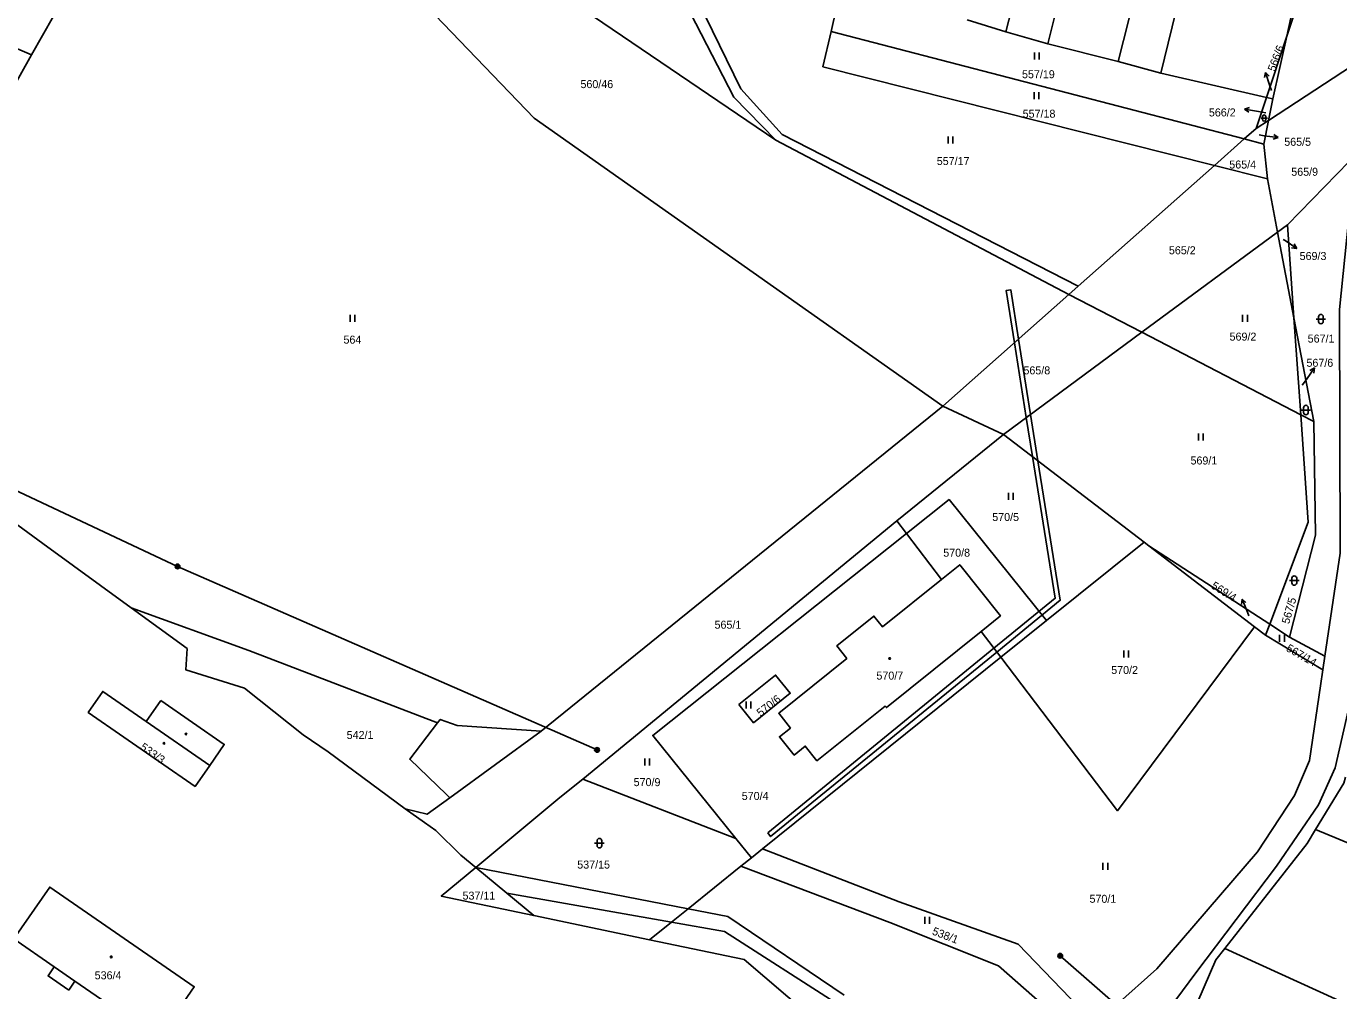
# Model space of a CAD drawing. Extents: x -757266 to -753360, y -1162585 to -1157740.
# Drawn here: x -756391.6 to -756112.8, y -1161498.7 to -1161293.7 of the extents above; entities that cross this region are included whole.
import ezdxf

# ---------------------------------------------------------------- set-up
doc = ezdxf.new("R2010")
doc.units = 0
for name, color, linetype in [('Hranice parcel', 7, 'Continuous'), ('Parcelní čísla', 7, 'Continuous'), ('Pop  PČ popisy', 7, 'Continuous'), ('Poz předměty', 7, 'Continuous'), ('Vnitřní kresba', 7, 'Continuous'), ('Věcná břemena k části', 7, 'Continuous'), ('Značky budov', 7, 'Continuous'), ('Značky kultur', 7, 'Continuous')]:
    doc.layers.add(name, color=color, linetype=linetype)

msp = doc.modelspace()

# ---------------------------------------------------------------- linework, layer by layer
at = {"layer": 'Hranice parcel'}
for p, q in [((-756183.54, -1161294.9), (-756158.99, -1161200.59)), ((-756159.65, -1161301.26), (-756140.24, -1161223.45)), ((-756150.62, -1161303.75), (-756133.64, -1161234.26)), ((-756232.35, -1161317.96), (-756311.49, -1161264.23)), ((-756376.54, -1161275.16), (-756390.46, -1161299.8)), ((-756183.54, -1161294.9), (-756191.74, -1161292.41)), ((-756132.86, -1161317.7), (-756220.64, -1161294.84)), ((-756174.59, -1161297.48), (-756183.54, -1161294.9)), ((-756128.17, -1161308.89), (-756123.86, -1161295.88)), ((-756123.86, -1161295.88), (-756126.82, -1161309.2)), ((-756159.65, -1161301.26), (-756174.59, -1161297.48)), ((-756390.46, -1161299.8), (-756397.42, -1161312.12)), ((-756150.62, -1161303.75), (-756159.65, -1161301.26)), ((-756128.17, -1161308.89), (-756150.62, -1161303.75)), ((-756130.35, -1161315.48), (-756128.17, -1161308.89)), ((-756126.82, -1161309.2), (-756128.17, -1161308.89)), ((-756126.82, -1161309.2), (-756127.73, -1161313.77)), ((-756132.86, -1161317.7), (-756130.35, -1161315.48)), ((-756127.73, -1161313.77), (-756130.35, -1161315.48)), ((-756128.73, -1161318.78), (-756127.73, -1161313.77)), ((-756232.35, -1161317.96), (-756170.13, -1161350.73)), ((-756139.21, -1161323.33), (-756132.86, -1161317.7)), ((-756128.73, -1161318.78), (-756132.86, -1161317.7)), ((-756127.96, -1161326.17), (-756128.73, -1161318.78)), ((-756139.21, -1161323.33), (-756168.18, -1161349.01)), ((-756127.96, -1161326.17), (-756139.21, -1161323.33)), ((-756110.57, -1161322.52), (-756123.68, -1161335.95)), ((-756125.79, -1161337.51), (-756127.96, -1161326.17)), ((-756125.79, -1161337.51), (-756154.62, -1161358.78)), ((-756123.68, -1161335.95), (-756125.79, -1161337.51)), ((-756122.31, -1161355.7), (-756125.79, -1161337.51)), ((-756122.31, -1161355.7), (-756123.68, -1161335.95)), ((-756170.13, -1161350.73), (-756168.18, -1161349.01)), ((-756170.13, -1161350.73), (-756196.92, -1161374.48)), ((-756154.62, -1161358.78), (-756170.13, -1161350.73)), ((-756120.89, -1161376.29), (-756122.31, -1161355.7)), ((-756122.31, -1161355.7), (-756118.1, -1161377.74)), ((-756184.02, -1161380.47), (-756154.62, -1161358.78)), ((-756120.89, -1161376.29), (-756154.62, -1161358.78)), ((-756184.02, -1161380.47), (-756196.92, -1161374.48)), ((-756118.1, -1161377.74), (-756120.89, -1161376.29)), ((-756206.66, -1161398.84), (-756184.02, -1161380.47)), ((-756154.15, -1161403.37), (-756184.02, -1161380.47)), ((-756273.4, -1161453.73), (-756206.66, -1161398.84)), ((-756206.66, -1161398.84), (-756204.62, -1161401.53)), ((-756197.18, -1161411.3), (-756204.62, -1161401.53)), ((-756154.15, -1161403.37), (-756174.87, -1161420.03)), ((-756153.17, -1161404.13), (-756154.15, -1161403.37)), ((-756130.72, -1161421.34), (-756153.17, -1161404.13)), ((-756153.17, -1161404.13), (-756127.46, -1161420.82)), ((-756174.87, -1161420.03), (-756184.59, -1161427.85)), ((-756128.34, -1161423.17), (-756130.72, -1161421.34)), ((-756128.34, -1161423.17), (-756127.46, -1161420.82)), ((-756127.46, -1161420.82), (-756123.26, -1161423.55)), ((-756184.59, -1161427.85), (-756188.79, -1161422.33)), ((-756116.17, -1161430.5), (-756128.34, -1161423.17)), ((-756123.26, -1161423.55), (-756115.74, -1161427.59)), ((-756184.59, -1161427.85), (-756235.19, -1161468.54)), ((-756115.74, -1161427.59), (-756116.17, -1161430.5)), ((-756240.87, -1161466.34), (-756273.4, -1161453.73)), ((-756237.56, -1161470.45), (-756240.87, -1161466.34)), ((-756235.19, -1161468.54), (-756237.56, -1161470.45)), ((-756237.56, -1161470.45), (-756239.79, -1161472.24)), ((-756259.22, -1161487.86), (-756283.77, -1161482.71))]:
    msp.add_line(p, q, dxfattribs=at)
for points in [[(-756390.46, -1161299.8), (-756481.22, -1161260.78), (-756640.9, -1161209.51), (-756684.73, -1161196.86)], [(-756174.59, -1161297.48), (-756167.09, -1161267.4), (-756151.83, -1161208.72)], [(-756196.92, -1161374.48), (-756283.73, -1161313.29), (-756324.07, -1161271.22), (-756357.02, -1161240.62)], [(-756272.42, -1161248.36), (-756241.28, -1161308.82), (-756232.35, -1161317.96)], [(-756168.18, -1161349.01), (-756231.02, -1161316.75), (-756239.84, -1161307.07), (-756265.47, -1161254.47)], [(-756123.86, -1161295.88), (-756121.39, -1161284.75), (-756121.69, -1161269.85)], [(-756123.86, -1161295.88), (-756120.03, -1161284.31), (-756121.69, -1161269.85)], [(-756220.64, -1161294.84), (-756219.55, -1161290.1), (-756217.24, -1161284.88)], [(-756139.21, -1161323.33), (-756222.36, -1161302.35), (-756220.64, -1161294.84)], [(-756097.95, -1161294.3), (-756102.88, -1161297.52), (-756105.97, -1161299.54), (-756127.73, -1161313.77)], [(-756110.57, -1161322.52), (-756109.94, -1161327.5), (-756112.65, -1161353.91), (-756112.52, -1161405.74), (-756115.74, -1161427.59)], [(-756369.33, -1161417.3), (-756388.09, -1161403.64), (-756428.45, -1161374.14), (-756432.89, -1161370.9)], [(-756304.22, -1161441.76), (-756303.68, -1161441.05), (-756300.04, -1161442.35), (-756282.26, -1161443.56), (-756196.92, -1161374.48)], [(-756127.46, -1161420.82), (-756119.31, -1161399.1), (-756120.89, -1161376.29)], [(-756118.1, -1161377.74), (-756117.77, -1161401.91), (-756123.26, -1161423.55)], [(-756204.62, -1161401.53), (-756195.59, -1161394.34), (-756174.87, -1161420.03)], [(-756204.62, -1161401.53), (-756258.51, -1161444.43), (-756240.87, -1161466.34)], [(-756197.18, -1161411.3), (-756193.32, -1161408.19), (-756184.68, -1161419.02), (-756188.79, -1161422.33)], [(-756188.79, -1161422.33), (-756208.9, -1161438.53), (-756209.17, -1161438.2), (-756223.64, -1161449.84), (-756226.14, -1161446.72), (-756228.46, -1161448.61), (-756231.62, -1161444.72), (-756229.28, -1161442.87), (-756231.77, -1161439.72), (-756217.31, -1161428.08), (-756219.42, -1161425.43), (-756211.54, -1161419.1), (-756209.69, -1161421.4), (-756197.18, -1161411.3)], [(-756304.22, -1161441.76), (-756344.31, -1161426.42), (-756369.33, -1161417.3)], [(-756311.11, -1161460.07), (-756327.45, -1161447.94), (-756332.78, -1161444.32), (-756345.23, -1161434.4), (-756357.68, -1161430.51), (-756357.42, -1161425.98), (-756369.33, -1161417.3)], [(-756130.72, -1161421.34), (-756159.77, -1161460.46), (-756184.59, -1161427.85)], [(-756240.23, -1161437.87), (-756232.44, -1161431.61), (-756229.31, -1161435.5), (-756237.1, -1161441.77), (-756240.23, -1161437.87)], [(-756116.17, -1161430.5), (-756116.67, -1161433.93), (-756118.99, -1161449.78), (-756122.19, -1161457.23), (-756130.08, -1161469.19), (-756151.46, -1161494.02), (-756159.98, -1161501.7), (-756162.48, -1161507.9)], [(-756363.02, -1161437.03), (-756366.1, -1161441.5), (-756375.37, -1161435.09), (-756378.42, -1161439.57), (-756355.74, -1161455.29), (-756352.64, -1161450.81), (-756349.56, -1161446.37), (-756363.02, -1161437.03)], [(-756159.42, -1161516.46), (-756154.69, -1161510.47), (-756143.16, -1161494.88), (-756126.02, -1161472.23), (-756117.13, -1161459.17), (-756113.58, -1161451.3), (-756109.9, -1161435.2), (-756109.66, -1161433.84)], [(-756311.11, -1161460.07), (-756306.45, -1161461.21), (-756301.62, -1161457.69), (-756302.35, -1161456.99), (-756310.15, -1161449.5), (-756304.22, -1161441.76)], [(-756296.1, -1161472.53), (-756278.27, -1161457.64), (-756273.4, -1161453.73)], [(-756117.72, -1161464.44), (-756111.7, -1161454.56), (-756111.36, -1161453.31)], [(-756296.1, -1161472.53), (-756299.31, -1161469.92), (-756304.62, -1161464.68), (-756307.04, -1161462.96), (-756311.11, -1161460.07)], [(-756137.01, -1161489.71), (-756119.54, -1161467.41), (-756117.72, -1161464.44)], [(-756117.72, -1161464.44), (-756097.06, -1161473.04), (-756071.31, -1161481.14), (-756032.92, -1161490.7), (-756008.46, -1161495.88), (-755947.24, -1161511.38)], [(-756162.48, -1161507.9), (-756180.93, -1161488.82), (-756206.15, -1161479.79), (-756235.19, -1161468.54)], [(-756283.77, -1161482.71), (-756303.45, -1161478.57), (-756296.1, -1161472.53)], [(-756283.77, -1161482.71), (-756289.5, -1161477.98), (-756296.1, -1161472.53)], [(-756239.79, -1161472.24), (-756251.03, -1161481.27), (-756254.57, -1161484.12), (-756259.22, -1161487.86)], [(-756164.37, -1161513.8), (-756165.06, -1161511.03), (-756185.05, -1161493.42), (-756208.18, -1161484.23), (-756239.79, -1161472.24)], [(-756382.56, -1161498.55), (-756386.98, -1161495.54), (-756385.64, -1161493.6), (-756394.23, -1161487.68), (-756386.63, -1161476.66), (-756355.93, -1161497.86), (-756358.14, -1161501.05), (-756356.8, -1161502.03), (-756357.72, -1161503.5), (-756359.15, -1161502.51), (-756363.54, -1161508.85), (-756364.7, -1161510.75), (-756368.03, -1161508.5), (-756366.74, -1161506.64), (-756381.25, -1161496.69), (-756382.56, -1161498.55)], [(-756312.03, -1161681.9), (-756299.84, -1161658.1), (-756263.6, -1161631.64), (-756226.26, -1161593.42), (-756207.13, -1161563.22), (-756211.76, -1161515.41), (-756239.08, -1161492.08), (-756259.22, -1161487.86)], [(-756145.4, -1161507.2), (-756138.89, -1161492.11), (-756137.01, -1161489.71)], [(-756137.01, -1161489.71), (-756105.47, -1161504.07), (-756095.47, -1161507.48), (-756049.15, -1161519.68), (-755945.92, -1161541.61), (-755925.02, -1161547.7)]]:
    msp.add_lwpolyline(points, dxfattribs=at)
at = {"layer": 'Pop  PČ popisy'}
for p, q in [((-756128.377, -1161303.556), (-756128.544, -1161304.663)), ((-756127.45, -1161306.41), (-756128.377, -1161303.556)), ((-756128.377, -1161303.556), (-756127.592, -1161304.354)), ((-756127.12, -1161307.42), (-756127.45, -1161306.41)), ((-756132.835, -1161311.349), (-756131.762, -1161311.03)), ((-756129.88, -1161311.87), (-756132.835, -1161311.349)), ((-756132.835, -1161311.349), (-756131.936, -1161312.016)), ((-756128.29, -1161312.16), (-756129.88, -1161311.87)), ((-756129.73, -1161316.85), (-756128.64, -1161317)), ((-756128.64, -1161317), (-756125.668, -1161317.418)), ((-756125.668, -1161317.418), (-756126.73, -1161317.774)), ((-756125.668, -1161317.418), (-756126.59, -1161316.782)), ((-756124.58, -1161339.03), (-756124.2, -1161339.29)), ((-756124.2, -1161339.29), (-756121.712, -1161340.968)), ((-756121.712, -1161340.968), (-756122.822, -1161340.823)), ((-756121.712, -1161340.968), (-756122.262, -1161339.993)), ((-756120.54, -1161370.03), (-756119.68, -1161368.79)), ((-756119.68, -1161368.79), (-756117.959, -1161366.332)), ((-756117.959, -1161366.332), (-756118.943, -1161366.865)), ((-756117.959, -1161366.332), (-756118.123, -1161367.439)), ((-756133.344, -1161415.488), (-756133.433, -1161416.604)), ((-756132.22, -1161418.27), (-756133.344, -1161415.488)), ((-756133.344, -1161415.488), (-756132.505, -1161416.228)), ((-756131.9, -1161419.06), (-756132.22, -1161418.27))]:
    msp.add_line(p, q, dxfattribs=at)
at = {"layer": 'Poz předměty'}
for p, q in [((-756441.37, -1161370.14), (-756359.45, -1161408.54)), ((-756359.45, -1161408.54), (-756270.36, -1161447.53)), ((-756171.96, -1161491.28), (-756099.89, -1161554.11))]:
    msp.add_line(p, q, dxfattribs=at)
for centre, radius in [((-756359.4534, -1161408.5399), 0.5), ((-756359.4534, -1161408.5399), 0.4), ((-756359.4534, -1161408.5399), 0.3), ((-756359.4534, -1161408.5399), 0.2), ((-756359.4534, -1161408.5399), 0.1), ((-756270.3634, -1161447.5299), 0.5), ((-756270.3634, -1161447.5299), 0.4), ((-756270.3634, -1161447.5299), 0.3), ((-756270.3634, -1161447.5299), 0.2), ((-756270.3634, -1161447.5299), 0.1), ((-756171.9634, -1161491.2799), 0.5), ((-756171.9634, -1161491.2799), 0.4), ((-756171.9634, -1161491.2799), 0.3), ((-756171.9634, -1161491.2799), 0.2), ((-756171.9634, -1161491.2799), 0.1)]:
    msp.add_circle(centre, radius, dxfattribs=at)
at = {"layer": 'Vnitřní kresba'}
for p, q in [((-756366.1, -1161441.5), (-756352.64, -1161450.81)), ((-756301.62, -1161457.69), (-756282.26, -1161443.56)), ((-756296.1, -1161472.53), (-756251.03, -1161481.27)), ((-756289.5, -1161477.98), (-756254.57, -1161484.12)), ((-756251.03, -1161481.27), (-756242.54, -1161482.92)), ((-756242.54, -1161482.92), (-756217.83, -1161499.63)), ((-756254.57, -1161484.12), (-756243.27, -1161486.11)), ((-756219.01, -1161501.67), (-756243.27, -1161486.11)), ((-756385.64, -1161493.6), (-756381.25, -1161496.69))]:
    msp.add_line(p, q, dxfattribs=at)
at = {"layer": 'Věcná břemena k části'}
for points in [[(-756181.71, -1161361), (-756180.82, -1161360.21), (-756182.49, -1161349.75), (-756183.48, -1161349.91)], [(-756178.26, -1161376.22), (-756180.82, -1161360.21), (-756181.71, -1161361), (-756179.17, -1161376.89)], [(-756177.84, -1161385.21), (-756176.69, -1161386.09), (-756178.26, -1161376.22), (-756179.17, -1161376.89)], [(-756234.11, -1161465.17), (-756233.48, -1161465.94), (-756185.44, -1161426.73), (-756171.95, -1161415.72), (-756176.69, -1161386.09), (-756177.84, -1161385.21), (-756173.03, -1161415.3), (-756186.05, -1161425.93)]]:
    msp.add_lwpolyline(points, close=True, dxfattribs=at)
at = {"layer": 'Značky budov'}
for centre in [(-756208.1968, -1161428.0992), (-756357.6768, -1161444.1492), (-756362.3568, -1161446.1092), (-756373.5568, -1161491.5092)]:
    msp.add_circle(centre, 0.175, dxfattribs=at)
at = {"layer": 'Značky kultur'}
for p, q in [((-756177.451, -1161300.8), (-756177.451, -1161299.3)), ((-756176.45, -1161300.8), (-756176.45, -1161299.3)), ((-756177.521, -1161309.27), (-756177.521, -1161307.77)), ((-756176.52, -1161309.27), (-756176.52, -1161307.77)), ((-756128.975, -1161312.925), (-756128.975, -1161313.596)), ((-756128.305, -1161313.596), (-756128.305, -1161312.925)), ((-756129.311, -1161313.261), (-756127.969, -1161313.261)), ((-756195.781, -1161318.69), (-756195.781, -1161317.19)), ((-756194.78, -1161318.69), (-756194.78, -1161317.19)), ((-756322.831, -1161356.57), (-756322.831, -1161355.07)), ((-756321.83, -1161356.57), (-756321.83, -1161355.07)), ((-756133.221, -1161356.54), (-756133.221, -1161355.04)), ((-756132.22, -1161356.54), (-756132.22, -1161355.04)), ((-756117.591, -1161355.981), (-756115.589, -1161355.981)), ((-756117.091, -1161355.481), (-756117.091, -1161356.482)), ((-756116.089, -1161356.482), (-756116.089, -1161355.481)), ((-756120.771, -1161375.301), (-756118.769, -1161375.301)), ((-756120.271, -1161374.801), (-756120.271, -1161375.802)), ((-756119.269, -1161375.802), (-756119.269, -1161374.801)), ((-756142.571, -1161381.77), (-756142.571, -1161380.27)), ((-756141.57, -1161381.77), (-756141.57, -1161380.27)), ((-756182.941, -1161394.4), (-756182.941, -1161392.9)), ((-756181.94, -1161394.4), (-756181.94, -1161392.9)), ((-756123.241, -1161411.531), (-756121.239, -1161411.531)), ((-756122.741, -1161411.031), (-756122.741, -1161412.032)), ((-756121.739, -1161412.032), (-756121.739, -1161411.031)), ((-756125.361, -1161424.58), (-756125.361, -1161423.08)), ((-756124.36, -1161424.58), (-756124.36, -1161423.08)), ((-756158.481, -1161427.89), (-756158.481, -1161426.39)), ((-756157.48, -1161427.89), (-756157.48, -1161426.39)), ((-756238.681, -1161438.75), (-756238.681, -1161437.25)), ((-756237.68, -1161438.75), (-756237.68, -1161437.25)), ((-756260.181, -1161450.82), (-756260.181, -1161449.32)), ((-756259.18, -1161450.82), (-756259.18, -1161449.32)), ((-756270.861, -1161467.341), (-756268.859, -1161467.341)), ((-756270.361, -1161466.841), (-756270.361, -1161467.842)), ((-756269.359, -1161467.842), (-756269.359, -1161466.841)), ((-756162.881, -1161473.03), (-756162.881, -1161471.53)), ((-756161.88, -1161473.03), (-756161.88, -1161471.53)), ((-756200.731, -1161484.49), (-756200.731, -1161482.99)), ((-756199.73, -1161484.49), (-756199.73, -1161482.99))]:
    msp.add_line(p, q, dxfattribs=at)
for centre, radius, start, end in [((-756128.64, -1161312.9256), 0.335, 0, 180), ((-756128.64, -1161313.5956), 0.335, 180, 359.987886), ((-756116.59, -1161355.4809), 0.5, 0, 180), ((-756116.59, -1161356.4809), 0.5, 180, 359.987886), ((-756119.77, -1161374.8009), 0.5, 0, 180), ((-756119.77, -1161375.8009), 0.5, 180, 359.987886), ((-756122.24, -1161411.0309), 0.5, 0, 180), ((-756122.24, -1161412.0309), 0.5, 180, 359.987886), ((-756269.86, -1161466.8409), 0.5, 0, 180), ((-756269.86, -1161467.8409), 0.5, 180, 359.987886)]:
    msp.add_arc(centre, radius, start, end, dxfattribs=at)

# ---------------------------------------------------------------- texts
at = {"layer": 'Parcelní čísla'}
for s, rotation, p in [('566/6', 68.999997, (-756126.376, -1161303.504)), ('569/4', 328, (-756140.04, -1161413.07)), ('567/5', 74, (-756123.342, -1161420.874)), ('567/14', 329.999997, (-756124.135, -1161426.396)), ('570/6', 38, (-756235.625, -1161440.53)), ('533/3', 325, (-756367.567, -1161447.286)), ('538/1', 339, (-756199.314, -1161486.693))]:
    msp.add_text(s, height=1.7, rotation=rotation, dxfattribs=at).set_placement(p)
for s, p in [('557/19', (-756180.08, -1161304.79)), ('560/46', (-756273.88, -1161306.89)), ('557/18', (-756179.94, -1161313.18)), ('566/2', (-756140.387, -1161312.91)), ('565/5', (-756124.38, -1161319.148)), ('557/17', (-756198.19, -1161323.24)), ('565/4', (-756136.05, -1161323.98)), ('565/9', (-756122.89, -1161325.52)), ('565/2', (-756148.88, -1161342.2)), ('569/3', (-756121.11, -1161343.418)), ('564', (-756324.22, -1161361.19)), ('569/2', (-756135.99, -1161360.55)), ('567/1', (-756119.4, -1161360.97)), ('565/8', (-756179.78, -1161367.72)), ('567/6', (-756119.66, -1161366.11)), ('569/1', (-756144.29, -1161386.87)), ('570/5', (-756186.408, -1161398.88)), ('570/8', (-756196.81, -1161406.47)), ('565/1', (-756245.4, -1161421.77)), ('570/2', (-756161.14, -1161431.39)), ('570/7', (-756211.01, -1161432.59)), ('542/1', (-756323.54, -1161445.2)), ('570/9', (-756262.58, -1161455.22)), ('570/4', (-756239.618, -1161458.16)), ('537/15', (-756274.557, -1161472.74)), ('537/11', (-756298.93, -1161479.34)), ('570/1', (-756165.75, -1161480.01)), ('536/4', (-756377.07, -1161496.27))]:
    msp.add_text(s, height=1.7, dxfattribs=at).set_placement(p)

doc.saveas('drawing.dxf')
